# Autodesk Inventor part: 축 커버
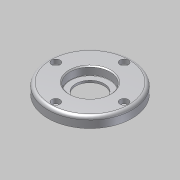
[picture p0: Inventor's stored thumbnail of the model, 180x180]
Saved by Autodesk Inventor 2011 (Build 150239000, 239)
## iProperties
Created: 2013-06
Part Number: 축 커버
Document SubType Name: Modeling
Designer: SeoGD™[esajin.kr]
Density: 1 g/cm^3
Author: SeoGD™[esajin.kr]
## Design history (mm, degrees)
sketch "스케치1"
  geometry: C1 r 40 at (0, 0) reference; C2 r 26 at (0, 0) reference; 1 further point
  node "참조1"
  node "참조2"
extrude "돌출1" new body sketch "스케치1" distance "d0" = 10; taper "d1" = 0 deg
extrude "돌출2" join sketch "스케치1" distance "d2" = 3; taper "d3" = 0 deg
hole "구멍1" diameter "d6" = 27; stored, may be unused: countersink angle "d10" = 90 deg, drill point angle "d12" = 118 deg; dims "d4" = 10, "d5" = 10, "d7" = 6, "d8" = 38, "d9" = 8, "d11" = 8
sketch "스케치2"
  geometry: C1 r 20 at (0, 0); 1 further point
  constraints: 1 centre point, 1 coincident
  dimensions: "d13" = 40 diameter of C1
extrude "돌출3" cut sketch "스케치2" distance "d14" = 3; taper "d15" = 0 deg
sketch "스케치3"
  geometry: C1 r 1.621 at (0, 32.5) reference; 1 further point
hole "구멍2" sketch "스케치3" at (0, 32.5) diameter "d16" = 4.5; stored, may be unused: countersink angle "d20" = 90 deg, drill point angle "d22" = 118 deg; dims "d17" = 6, "d18" = 8, "d19" = 4.4, "d21" = 8
fillet "모깎기1" dims "d26" = 3, "d27" = 0.3
chamfer "모따기1" distance "d28" = 1; stored, may be unused: second distance "d29" = 2, angle "d30" = 45 deg
node "솔리드1"
pattern_circular "원형 패턴1" dims angle "d24" = 360 deg
node "참조3"
